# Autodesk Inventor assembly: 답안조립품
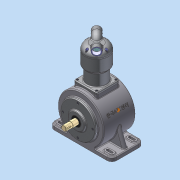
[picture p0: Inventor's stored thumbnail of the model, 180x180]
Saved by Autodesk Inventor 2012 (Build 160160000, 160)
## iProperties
Created: 2015-06
Part Number: 답안조립품
Document SubType Name: Assembly
Designer: Administrator
Author: Administrator
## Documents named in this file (15)
- C:\Users\Administrator\Desktop\450605V1027\답안조립품.iam
- C:\Users\Administrator\Desktop\450605V1027\본체.ipt
- C:\Users\Administrator\Desktop\450605V1027\메인 크랭크 축-구동부.ipt
- C:\Users\Administrator\Desktop\450605V1027\크랭크 서브축.ipt
- C:\Users\Administrator\Desktop\450605V1027\베어링 NA 4902.ipt
- C:\Users\Administrator\Desktop\450605V1027\커넥팅 로드.ipt
- C:\Users\Administrator\Desktop\450605V1027\피스톤.ipt
- C:\Users\Administrator\Desktop\450605V1027\피스톤 핀.ipt
- C:\Users\Administrator\Desktop\450605V1027\실린더.ipt
- C:\Users\Administrator\Desktop\450605V1027\실린더헤드.ipt
- C:\Users\Administrator\Desktop\450605V1027\베어링 6204.ipt
- C:\Users\Administrator\Desktop\450605V1027\메인커버.ipt
- C:\Users\Administrator\Desktop\450605V1027\M4x0.7.ipt
- C:\Users\Administrator\Desktop\450605V1027\M5x0.8.ipt
- C:\Users\Administrator\Desktop\450605V1027\오일실.ipt
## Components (14 placed, 4 different names)
1. 피스톤:1
2. 피스톤 핀:1
3. M4x0.7:1
4. M4x0.7:2
5. M4x0.7:3
6. M4x0.7:4
7. M4x0.7:5
8. M4x0.7:6
9. M4x0.7:7
10. M4x0.7:8
11. M5x0.8:1
12. M5x0.8:2
13. M5x0.8:3
14. M5x0.8:4
